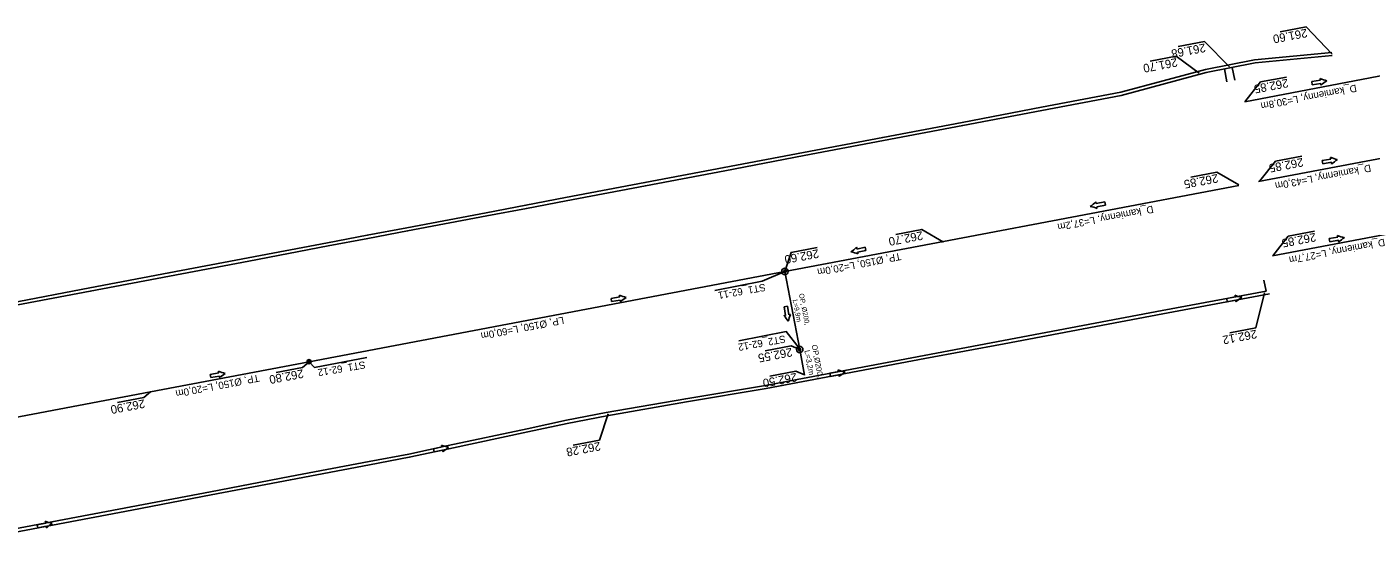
# Model space of a CAD drawing. Extents: x -1 to 65640748, y -22 to 5530284.
# Drawn here: x 6556170.8 to 6556337.3, y 5528424 to 5528487.5 of the extents above; entities that cross this region are included whole.
import ezdxf

# ---------------------------------------------------------------- set-up
doc = ezdxf.new("R2010")
doc.units = 0
for name, color, linetype in [('TOR_PROF-studnie i osadniki', 7, 'Continuous'), ('TOR_PS_ODW-drenaze', 7, 'Continuous'), ('TOR_PS_ODW-drenokolektory', 7, 'Continuous'), ('TOR_PS_ODW-kolektory', 7, 'Continuous'), ('TOR_PS_ODW-studnie PEHD', 7, 'Continuous'), ('TOR_PS_OPIS_O-opisy rurociagow', 7, 'Continuous'), ('TOR_PS_OPIS_O-opisy studni', 7, 'Continuous'), ('TOR_PS_OPIS_T-INFO', 7, 'Continuous'), ('TOR_PS_T-rowy otwarte umocnione', 7, 'Continuous')]:
    doc.layers.add(name, color=color, linetype=linetype)

msp = doc.modelspace()

# ---------------------------------------------------------------- linework, layer by layer
at = {"layer": 'TOR_PROF-studnie i osadniki'}
for radius in [0.25, 0.125]:
    msp.add_circle((6556205.77, 5528446.05), radius, dxfattribs=at)
at = {"layer": 'TOR_PS_ODW-drenaze'}
for p, q in [((6556351.96, 5528483.99), (6556321.7, 5528478.25)), ((6556365.65, 5528476.36), (6556323.4, 5528468.35))]:
    msp.add_line(p, q, dxfattribs=at)
for points in [[(6556320.95, 5528467.88), (6556284.37, 5528460.95)], [(6556352.35, 5528464.32), (6556325.13, 5528459.16)], [(6556284.37, 5528460.95), (6556264.72, 5528457.22)], [(6556205.77, 5528446.05), (6556186.12, 5528442.33)], [(6556186.12, 5528442.33), (6556125.4, 5528430.81), (6556122.44, 5528429.39), (6556117.5, 5528428.45)]]:
    msp.add_lwpolyline(points, dxfattribs=at)
at = {"layer": 'TOR_PS_ODW-drenokolektory'}
msp.add_lwpolyline([(6556264.72, 5528457.22), (6556205.77, 5528446.05)], dxfattribs=at)
at = {"layer": 'TOR_PS_ODW-kolektory'}
for p, q in [((6556264.72, 5528457.22), (6556266.55, 5528447.55)), ((6556266.55, 5528447.55), (6556267.16, 5528444.37))]:
    msp.add_line(p, q, dxfattribs=at)
at = {"layer": 'TOR_PS_ODW-studnie PEHD'}
for centre, radius in [((6556264.72, 5528457.22), 0.4), ((6556264.72, 5528457.22), 0.145), ((6556266.55, 5528447.55), 0.4), ((6556266.55, 5528447.55), 0.145), ((6556205.77, 5528446.05), 0.25), ((6556205.77, 5528446.05), 0.112)]:
    msp.add_circle(centre, radius, dxfattribs=at)
at = {"layer": 'TOR_PS_OPIS_O-opisy rurociagow'}
for p, q in [((6556331.05, 5528480.91), (6556329.97, 5528480.73)), ((6556331.05, 5528480.91), (6556329.97, 5528480.73)), ((6556329.97, 5528480.73), (6556330.04, 5528480.33)), ((6556329.97, 5528480.73), (6556330.04, 5528480.33)), ((6556330.04, 5528480.33), (6556331.12, 5528480.52)), ((6556331.12, 5528480.52), (6556330.04, 5528480.33)), ((6556332.35, 5528471.14), (6556331.27, 5528470.95)), ((6556332.35, 5528471.14), (6556331.27, 5528470.95)), ((6556331.27, 5528470.95), (6556331.34, 5528470.56)), ((6556331.27, 5528470.95), (6556331.34, 5528470.56)), ((6556331.34, 5528470.56), (6556332.42, 5528470.74)), ((6556332.42, 5528470.74), (6556331.34, 5528470.56)), ((6556303.26, 5528465.62), (6556304.33, 5528465.84)), ((6556303.26, 5528465.62), (6556304.33, 5528465.84)), ((6556304.41, 5528465.45), (6556303.34, 5528465.23)), ((6556303.34, 5528465.23), (6556304.41, 5528465.45)), ((6556304.33, 5528465.84), (6556304.41, 5528465.45)), ((6556304.33, 5528465.84), (6556304.41, 5528465.45)), ((6556273.61, 5528460), (6556274.68, 5528460.22)), ((6556273.61, 5528460), (6556274.68, 5528460.22)), ((6556274.68, 5528460.22), (6556274.76, 5528459.83)), ((6556274.68, 5528460.22), (6556274.76, 5528459.83)), ((6556333.22, 5528461.48), (6556332.15, 5528461.29)), ((6556333.22, 5528461.48), (6556332.15, 5528461.29)), ((6556332.15, 5528461.29), (6556332.22, 5528460.9)), ((6556332.15, 5528461.29), (6556332.22, 5528460.9)), ((6556332.22, 5528460.9), (6556333.29, 5528461.08)), ((6556333.29, 5528461.08), (6556332.22, 5528460.9)), ((6556274.76, 5528459.83), (6556273.69, 5528459.61)), ((6556273.69, 5528459.61), (6556274.76, 5528459.83)), ((6556244.26, 5528454.08), (6556243.19, 5528453.89)), ((6556244.26, 5528454.08), (6556243.19, 5528453.89)), ((6556243.19, 5528453.89), (6556243.25, 5528453.5)), ((6556243.19, 5528453.89), (6556243.25, 5528453.5)), ((6556243.25, 5528453.5), (6556244.33, 5528453.68)), ((6556244.33, 5528453.68), (6556243.25, 5528453.5)), ((6556320.51, 5528454.07), (6556319.44, 5528453.87)), ((6556320.51, 5528454.07), (6556319.44, 5528453.87)), ((6556319.44, 5528453.87), (6556319.51, 5528453.48)), ((6556319.44, 5528453.87), (6556319.51, 5528453.48)), ((6556319.51, 5528453.48), (6556320.59, 5528453.68)), ((6556320.59, 5528453.68), (6556319.51, 5528453.48)), ((6556265.02, 5528452.92), (6556264.62, 5528452.85)), ((6556265.02, 5528452.92), (6556264.62, 5528452.85)), ((6556264.62, 5528452.85), (6556264.81, 5528451.77)), ((6556264.81, 5528451.77), (6556264.62, 5528452.85)), ((6556265.2, 5528451.84), (6556265.02, 5528452.92)), ((6556265.2, 5528451.84), (6556265.02, 5528452.92)), ((6556194.6, 5528444.66), (6556193.53, 5528444.48)), ((6556194.6, 5528444.66), (6556193.53, 5528444.48)), ((6556193.53, 5528444.48), (6556193.59, 5528444.08)), ((6556193.53, 5528444.48), (6556193.59, 5528444.08)), ((6556193.59, 5528444.08), (6556194.67, 5528444.27)), ((6556194.67, 5528444.27), (6556193.59, 5528444.08)), ((6556271.38, 5528444.83), (6556270.3, 5528444.63)), ((6556271.38, 5528444.83), (6556270.3, 5528444.63)), ((6556270.3, 5528444.63), (6556270.38, 5528444.23)), ((6556270.3, 5528444.63), (6556270.38, 5528444.23)), ((6556270.38, 5528444.23), (6556271.45, 5528444.44)), ((6556271.45, 5528444.44), (6556270.38, 5528444.23)), ((6556222.25, 5528435.49), (6556221.18, 5528435.27)), ((6556222.25, 5528435.49), (6556221.18, 5528435.27)), ((6556221.18, 5528435.27), (6556221.27, 5528434.87)), ((6556221.18, 5528435.27), (6556221.27, 5528434.87)), ((6556221.27, 5528434.87), (6556222.34, 5528435.1)), ((6556222.34, 5528435.1), (6556221.27, 5528434.87)), ((6556173.16, 5528426.07), (6556172.09, 5528425.86)), ((6556173.16, 5528426.07), (6556172.09, 5528425.86)), ((6556172.09, 5528425.86), (6556172.16, 5528425.47)), ((6556172.09, 5528425.86), (6556172.16, 5528425.47)), ((6556172.16, 5528425.47), (6556173.23, 5528425.68)), ((6556173.23, 5528425.68), (6556172.16, 5528425.47))]:
    msp.add_line(p, q, dxfattribs=at)
for points in [[(6556331, 5528481.13), (6556331, 5528481.13)], [(6556331.15, 5528480.3), (6556331.15, 5528480.3)], [(6556332.3, 5528471.36), (6556332.3, 5528471.36)], [(6556332.45, 5528470.52), (6556332.45, 5528470.52)], [(6556303.22, 5528465.85), (6556303.22, 5528465.85)], [(6556303.39, 5528465.01), (6556303.39, 5528465.01)], [(6556273.58, 5528460.23), (6556273.58, 5528460.23)], [(6556333.17, 5528461.7), (6556333.17, 5528461.7)], [(6556333.32, 5528460.86), (6556333.32, 5528460.86)], [(6556273.75, 5528459.39), (6556273.75, 5528459.39)], [(6556244.21, 5528454.3), (6556244.21, 5528454.3)], [(6556244.36, 5528453.46), (6556244.36, 5528453.46)], [(6556320.46, 5528454.29), (6556320.46, 5528454.29)], [(6556265.42, 5528451.89), (6556265.42, 5528451.89)], [(6556320.62, 5528453.46), (6556320.62, 5528453.46)], [(6556264.59, 5528451.74), (6556264.59, 5528451.74)], [(6556194.55, 5528444.88), (6556194.55, 5528444.88)], [(6556194.7, 5528444.05), (6556194.7, 5528444.05)], [(6556271.32, 5528445.05), (6556271.32, 5528445.05)], [(6556271.48, 5528444.21), (6556271.48, 5528444.21)], [(6556222.19, 5528435.71), (6556222.19, 5528435.71)], [(6556222.37, 5528434.88), (6556222.37, 5528434.88)], [(6556173.11, 5528426.29), (6556173.11, 5528426.29)], [(6556173.27, 5528425.45), (6556173.27, 5528425.45)]]:
    msp.add_lwpolyline(points, dxfattribs=at)
for centre, radius, start, end in [((6556332.99, 5528485.63), 4.92, 246.1449, 256.5268), ((6556331.46, 5528481.12), 0.458, 178.2595, 206.7208), ((6556332.99, 5528485.63), 4.92, 246.1449, 256.5268), ((6556331.46, 5528481.12), 0.458, 178.2595, 206.7208), ((6556331.57, 5528480.46), 0.458, 172.9889, 201.4501), ((6556331.57, 5528480.46), 0.458, 172.9889, 201.4501), ((6556334.53, 5528476.73), 4.92, 123.1828, 133.5647), ((6556334.53, 5528476.73), 4.92, 123.1828, 133.5647), ((6556334.29, 5528475.86), 4.92, 246.1449, 256.5268), ((6556332.76, 5528471.34), 0.458, 178.2595, 206.7208), ((6556334.29, 5528475.86), 4.92, 246.1449, 256.5268), ((6556332.76, 5528471.34), 0.458, 178.2595, 206.7208), ((6556332.87, 5528470.69), 0.458, 172.9889, 201.4501), ((6556332.87, 5528470.69), 0.458, 172.9889, 201.4501), ((6556335.84, 5528466.96), 4.92, 123.1828, 133.5647), ((6556335.84, 5528466.96), 4.92, 123.1828, 133.5647), ((6556299.72, 5528469.3), 4.92, 304.9397, 315.3215), ((6556299.72, 5528469.3), 4.92, 304.9397, 315.3215), ((6556301.54, 5528460.46), 4.92, 67.9018, 78.2836), ((6556301.54, 5528460.46), 4.92, 67.9018, 78.2836), ((6556302.8, 5528465.67), 0.458, 354.7457, 23.207), ((6556302.8, 5528465.67), 0.458, 354.7457, 23.207), ((6556302.93, 5528465.01), 0.458, 0.0164, 28.4776), ((6556302.93, 5528465.01), 0.458, 0.0164, 28.4776), ((6556270.08, 5528463.68), 4.92, 304.9397, 315.3215), ((6556270.08, 5528463.68), 4.92, 304.9397, 315.3215), ((6556273.16, 5528460.05), 0.458, 354.7457, 23.207), ((6556273.16, 5528460.05), 0.458, 354.7457, 23.207), ((6556335.16, 5528466.19), 4.92, 246.1449, 256.5268), ((6556333.63, 5528461.68), 0.458, 178.2595, 206.7208), ((6556335.16, 5528466.19), 4.92, 246.1449, 256.5268), ((6556333.63, 5528461.68), 0.458, 178.2595, 206.7208), ((6556333.75, 5528461.03), 0.458, 172.9889, 201.4501), ((6556333.75, 5528461.03), 0.458, 172.9889, 201.4501), ((6556336.71, 5528457.3), 4.92, 123.1828, 133.5647), ((6556336.71, 5528457.3), 4.92, 123.1828, 133.5647), ((6556271.9, 5528454.84), 4.92, 67.9018, 78.2836), ((6556271.9, 5528454.84), 4.92, 67.9018, 78.2836), ((6556273.29, 5528459.39), 0.458, 0.0164, 28.4776), ((6556273.29, 5528459.39), 0.458, 0.0164, 28.4776), ((6556246.2, 5528458.79), 4.92, 246.1449, 256.5268), ((6556244.67, 5528454.28), 0.458, 178.2595, 206.7208), ((6556246.2, 5528458.79), 4.92, 246.1449, 256.5268), ((6556244.67, 5528454.28), 0.458, 178.2595, 206.7208), ((6556244.79, 5528453.63), 0.458, 172.9889, 201.4501), ((6556244.79, 5528453.63), 0.458, 172.9889, 201.4501), ((6556247.75, 5528449.9), 4.92, 123.1828, 133.5647), ((6556247.75, 5528449.9), 4.92, 123.1828, 133.5647), ((6556322.39, 5528458.82), 4.92, 246.9506, 257.3325), ((6556320.92, 5528454.29), 0.458, 179.0652, 207.5264), ((6556322.39, 5528458.82), 4.92, 246.9506, 257.3325), ((6556320.92, 5528454.29), 0.458, 179.0652, 207.5264), ((6556321.04, 5528453.63), 0.458, 173.7945, 202.2558), ((6556321.04, 5528453.63), 0.458, 173.7945, 202.2558), ((6556324.06, 5528449.94), 4.92, 123.9885, 134.3703), ((6556324.06, 5528449.94), 4.92, 123.9885, 134.3703), ((6556269.92, 5528449.9), 4.92, 156.1449, 166.5268), ((6556269.92, 5528449.9), 4.92, 156.1449, 166.5268), ((6556265.41, 5528451.43), 0.458, 88.2595, 116.7208), ((6556265.41, 5528451.43), 0.458, 88.2595, 116.7208), ((6556264.75, 5528451.32), 0.458, 82.9889, 111.4501), ((6556264.75, 5528451.32), 0.458, 82.9889, 111.4501), ((6556261.02, 5528448.36), 4.92, 33.1828, 43.5647), ((6556261.02, 5528448.36), 4.92, 33.1828, 43.5647), ((6556196.54, 5528449.38), 4.92, 246.1449, 256.5268), ((6556195.01, 5528444.87), 0.458, 178.2595, 206.7208), ((6556196.54, 5528449.38), 4.92, 246.1449, 256.5268), ((6556195.01, 5528444.87), 0.458, 178.2595, 206.7208), ((6556195.13, 5528444.21), 0.458, 172.9889, 201.4501), ((6556195.13, 5528444.21), 0.458, 172.9889, 201.4501), ((6556198.09, 5528440.48), 4.92, 123.1828, 133.5647), ((6556198.09, 5528440.48), 4.92, 123.1828, 133.5647), ((6556273.25, 5528449.57), 4.92, 246.9461, 257.3279), ((6556271.78, 5528445.04), 0.458, 179.0606, 207.5219), ((6556273.25, 5528449.57), 4.92, 246.9461, 257.3279), ((6556271.78, 5528445.04), 0.458, 179.0606, 207.5219), ((6556271.9, 5528444.39), 0.458, 173.79, 202.2512), ((6556271.9, 5528444.39), 0.458, 173.79, 202.2512), ((6556274.92, 5528440.7), 4.92, 123.9839, 134.3658), ((6556274.92, 5528440.7), 4.92, 123.9839, 134.3658), ((6556224, 5528440.29), 4.92, 248.3977, 258.7795), ((6556222.65, 5528435.72), 0.458, 180.5123, 208.9735), ((6556224, 5528440.29), 4.92, 248.3977, 258.7795), ((6556222.65, 5528435.72), 0.458, 180.5123, 208.9735), ((6556225.9, 5528431.45), 4.92, 125.4356, 135.8174), ((6556225.9, 5528431.45), 4.92, 125.4356, 135.8174), ((6556222.79, 5528435.07), 0.458, 175.2416, 203.7029), ((6556222.79, 5528435.07), 0.458, 175.2416, 203.7029), ((6556175.02, 5528430.82), 4.92, 247.045, 257.4268), ((6556173.56, 5528426.28), 0.458, 179.1595, 207.6208), ((6556175.02, 5528430.82), 4.92, 247.045, 257.4268), ((6556173.56, 5528426.28), 0.458, 179.1595, 207.6208), ((6556173.69, 5528425.63), 0.458, 173.8889, 202.3501), ((6556173.69, 5528425.63), 0.458, 173.8889, 202.3501), ((6556176.71, 5528421.94), 4.92, 124.0829, 134.4647), ((6556176.71, 5528421.94), 4.92, 124.0829, 134.4647)]:
    msp.add_arc(centre, radius, start, end, dxfattribs=at)
at = {"layer": 'TOR_PS_OPIS_T-INFO'}
for points in [[(6556332.49, 5528484.13), (6556329.28, 5528487.51), (6556326.05, 5528486.89)], [(6556319.79, 5528482.57), (6556316.68, 5528485.69), (6556313.45, 5528485.07)], [(6556316.03, 5528481.8), (6556313.2, 5528483.88), (6556309.97, 5528483.26)], [(6556321.7, 5528478.25), (6556323.63, 5528480.69), (6556326.87, 5528481.29)], [(6556323.56, 5528468.46), (6556325.49, 5528470.89), (6556328.73, 5528471.5)], [(6556320.93, 5528467.96), (6556318.24, 5528469.52), (6556315.01, 5528468.9)], [(6556284.36, 5528460.87), (6556281.67, 5528462.43), (6556278.44, 5528461.81)], [(6556325.14, 5528459.17), (6556327.07, 5528461.61), (6556330.3, 5528462.21)], [(6556264.72, 5528457.22), (6556265.48, 5528459.59), (6556268.72, 5528460.19)], [(6556264.72, 5528457.22), (6556261.92, 5528456.02), (6556256.02, 5528454.88)], [(6556324.11, 5528454.57), (6556323.05, 5528450.24), (6556319.81, 5528449.61)], [(6556266.48, 5528447.71), (6556264.89, 5528449.78), (6556259, 5528448.64)], [(6556266.55, 5528447.55), (6556265.5, 5528448), (6556262.26, 5528447.38)], [(6556205.77, 5528446.05), (6556204.95, 5528445.34), (6556201.71, 5528444.71)], [(6556205.77, 5528446.05), (6556206.44, 5528445.34), (6556212.92, 5528446.55)], [(6556267.13, 5528444.44), (6556266.08, 5528444.89), (6556262.84, 5528444.27)], [(6556186.12, 5528442.33), (6556185.3, 5528441.61), (6556182.06, 5528440.99)], [(6556242.84, 5528439.61), (6556241.74, 5528436.35), (6556238.5, 5528435.72)]]:
    msp.add_lwpolyline(points, dxfattribs=at)
at = {"layer": 'TOR_PS_T-rowy otwarte umocnione'}
for p, q in [((6556319.45, 5528480.71), (6556319.15, 5528482.3)), ((6556320.43, 5528480.9), (6556320.13, 5528482.49)), ((6556324.06, 5528456.14), (6556324.32, 5528454.79))]:
    msp.add_line(p, q, dxfattribs=at)
for points in [[(6556322.89, 5528483.45), (6556316.82, 5528482.25), (6556306.31, 5528479.42), (6556296.49, 5528477.56), (6556286.67, 5528475.69), (6556276.84, 5528473.83), (6556267.02, 5528471.96), (6556257.19, 5528470.1), (6556247.37, 5528468.23), (6556237.54, 5528466.37), (6556232.63, 5528465.43), (6556227.72, 5528464.5), (6556217.89, 5528462.64), (6556212.98, 5528461.7), (6556208.07, 5528460.77), (6556198.24, 5528458.91), (6556188.42, 5528457.04), (6556178.6, 5528455.18), (6556168.77, 5528453.31)], [(6556332.48, 5528484.32), (6556322.89, 5528483.45)], [(6556332.51, 5528483.97), (6556322.96, 5528483.05)], [(6556322.96, 5528483.05), (6556316.9, 5528481.85), (6556306.39, 5528479.03), (6556296.56, 5528477.16), (6556286.74, 5528475.3), (6556276.92, 5528473.43), (6556267.09, 5528471.57), (6556257.27, 5528469.7), (6556247.44, 5528467.84), (6556237.62, 5528465.97), (6556232.7, 5528465.04), (6556227.79, 5528464.11), (6556217.97, 5528462.24), (6556213.06, 5528461.31), (6556208.14, 5528460.38), (6556198.32, 5528458.51), (6556188.49, 5528456.65), (6556178.67, 5528454.78), (6556168.85, 5528452.92)], [(6556324.32, 5528454.79), (6556311.44, 5528452.37), (6556301.62, 5528450.52), (6556291.79, 5528448.67), (6556281.96, 5528446.82), (6556272.13, 5528444.97), (6556262.3, 5528443.12), (6556252.44, 5528441.45), (6556242.59, 5528439.74), (6556237.68, 5528438.8), (6556232.79, 5528437.75), (6556223.01, 5528435.66), (6556218.12, 5528434.61), (6556213.2, 5528433.68), (6556203.38, 5528431.81), (6556193.56, 5528429.94), (6556183.73, 5528428.08), (6556173.91, 5528426.21), (6556164.08, 5528424.34)], [(6556324.74, 5528454.46), (6556311.52, 5528451.97), (6556301.69, 5528450.13), (6556291.86, 5528448.28), (6556282.03, 5528446.43), (6556272.21, 5528444.58), (6556262.38, 5528442.73), (6556252.52, 5528441.06), (6556242.66, 5528439.34), (6556237.75, 5528438.41), (6556232.86, 5528437.36), (6556223.08, 5528435.26), (6556218.19, 5528434.22), (6556213.28, 5528433.28), (6556203.46, 5528431.42), (6556193.63, 5528429.55), (6556183.81, 5528427.68), (6556173.98, 5528425.82), (6556164.16, 5528423.95)]]:
    msp.add_lwpolyline(points, dxfattribs=at)

# ---------------------------------------------------------------- texts
at = {"layer": 'TOR_PS_OPIS_O-opisy rurociagow'}
for s, height, rotation, p in [('D_kamienny, L=30,8m', 0.9, 190.7332, (6556335.45, 5528480.37)), ('D_kamienny, L=43,0m', 0.9, 190.7332, (6556337.23, 5528470.48)), ('D_kamienny, L=37,2m', 0.9, 190.7332, (6556310.28, 5528465.38)), ('D_kamienny, L=27,7m', 0.9, 190.7332, (6556338.96, 5528461.29)), ('TP, Ø150, L=20,0m', 0.9, 190.9157, (6556279.01, 5528459.54)), ('L=9,9m', 0.61, 280.821, (6556265.67, 5528453.7)), ('OP, Ø200, ', 0.61, 280.821, (6556266.46, 5528454.44)), ('LP, Ø150, L=60,0m', 0.9, 190.9157, (6556237.26, 5528451.63)), ('L=3,2m', 0.675, 280.821, (6556267.13, 5528447.42)), ('OP,Ø200, ', 0.675, 280.821, (6556268.03, 5528448.1)), ('TP, Ø150, L=20,0m', 0.9, 190.9157, (6556199.52, 5528444.48))]:
    msp.add_text(s, height=height, rotation=rotation, dxfattribs=at).set_placement(p)
at = {"layer": 'TOR_PS_OPIS_O-opisy studni'}
for s, rotation, p in [('ST1_62-11', 190.1374, (6556262.24, 5528455.72)), ('ST2_62-12', 190.2935, (6556264.72, 5528449.32)), ('ST1_62-12', 189.7442, (6556212.67, 5528446.12))]:
    msp.add_text(s, height=0.9, rotation=rotation, dxfattribs=at).set_placement(p)
at = {"layer": 'TOR_PS_OPIS_T-INFO'}
for s, rotation, p in [('261.60', 190.7159, (6556329.32, 5528487.29)), ('261.68', 190.7159, (6556316.72, 5528485.46)), ('261.70', 190.7159, (6556313.24, 5528483.66)), ('262.85', 190.7506, (6556326.97, 5528481.09)), ('262.85', 190.7506, (6556328.83, 5528471.29)), ('262.85', 190.7159, (6556318.28, 5528469.3)), ('262.70', 190.7159, (6556281.71, 5528462.21)), ('262.85', 190.7506, (6556330.41, 5528462.01)), ('262.60', 190.7506, (6556268.82, 5528459.98)), ('262.12', 190.7159, (6556323.08, 5528450.01)), ('262.55', 190.7159, (6556265.54, 5528447.77)), ('262.80', 190.7159, (6556204.99, 5528445.11)), ('262.50', 190.7159, (6556266.12, 5528444.67)), ('262.90', 190.7159, (6556185.34, 5528441.39)), ('262.28', 190.7159, (6556241.78, 5528436.12))]:
    msp.add_text(s, height=1.05, rotation=rotation, dxfattribs=at).set_placement(p)

doc.saveas('drawing.dxf')
